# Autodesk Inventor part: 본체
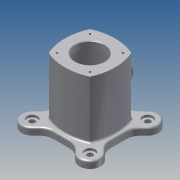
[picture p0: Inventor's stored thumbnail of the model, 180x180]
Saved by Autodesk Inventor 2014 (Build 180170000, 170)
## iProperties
Created: 2016-05
Part Number: 본체
Material: 알루미늄 6061
Document SubType Name: Modeling
Designer: 702
Density: 2.71 g/cm^3
Appearance: 알루미늄 - 평지
Mass: 1109.03 g
Surface Area: 865.354 cm^2
Volume: 409.236 cm^3
Author: 702
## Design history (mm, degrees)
sketch "스케치1"
  geometry: L1 (-49, -49)-(49, -49); L2 (49, -49)-(49, 49); L3 (49, 49)-(-49, 49); L4 (-49, 49)-(-49, -49); L5 (-49, -49)-(49, 49); L6 (49, -49)-(-49, 49); L7 (0, 0)-(-70, 0); L8 (0, 0)-(-49.497, 49.497); L9 (-36.77, 62.225)-(-23.544, 49); L10 (-62.225, 36.77)-(-49, 23.544); L11 (-49, 23.544)-(-49, 49); L12 (-49, 49)-(-23.544, 49); A1 r 70 centre (0, 0) between (-70, 0) and (-49.497, 49.497); A2 r 18 centre (-49.497, 49.497) between (-35.239, 60.483) and (-60.483, 35.239); A3 r 18 centre (-49.497, 49.497) between (-31.504, 49) and (-35.239, 60.483); A4 r 18 centre (-49.497, 49.497) between (-49, 31.504) and (-31.504, 49); A5 r 18 centre (-49.497, 49.497) between (-60.483, 35.239) and (-49, 31.504); 1 further point
  constraints: 24 end point, 18 point on circle, 6 tangent, 5 centre point, 4 midpoint, 4 point on line, 2 coincident, 2 collinear, 2 parallel, 2 perpendicular, 1 horizontal
  dimensions: "d0" = 98 distance of L2.end L3.end; "d1" = 98 distance of L1.end L2.end; "d2" = 140 diameter of A1; "d3" = 45 deg angle of L7 L8; "d4" = 36 diameter of A2; "d5" = 45 deg angle of L3 L9; "d6" = 45 deg angle of L10 L4
extrude "돌출1" new body sketch "스케치1" distance "d7" = 12; taper "d8" = 0 deg
extrude "돌출2" join sketch "스케치1" distance "d9" = 12; taper "d10" = 0 deg
hole "구멍1" diameter "d13" = 10; stored, may be unused: countersink angle "d17" = 90 deg, drill point angle "d19" = 118 deg; dims "d11" = 10, "d12" = 10, "d14" = 6, "d15" = 18, "d16" = 4, "d18" = 8
sketch "스케치3"
  geometry: L1 (-23.544, -49)-(-36.77, -62.225) reference; L2 (23.544, -49)-(-23.544, -49) reference; L3 (-40, 0)-(0, 0); L4 (0, 0)-(-28.284, 28.284); A1 r 40 centre (0, 0) between (-40, 0) and (-28.284, 28.284); 2 further points
  constraints: 4 end point, 2 coincident, 2 point on circle, 1 centre point, 1 parallel, 1 perpendicular
  dimensions: "d24" = 80 diameter of A1
hole "구멍2" sketch "스케치3" at (-28.284, 28.284) diameter "d25" = 3.242; stored, may be unused: countersink angle "d29" = 90 deg, drill point angle "d31" = 118 deg; dims "d26" = 7, "d27" = 4, "d28" = 2, "d30" = 10
sketch "스케치4"
  geometry: L1 (43, -43)-(-43, -43); L2 (-43, -43)-(-43, 43); L3 (-43, 43)-(43, 43); L4 (43, 43)-(43, -43); L5 (43, -43)-(-43, 43); L6 (-43, -43)-(43, 43); L7 (-35.355, -35.355)-(35.355, 35.355); L8 (-35.355, 35.355)-(35.355, -35.355); L9 (-23.544, -49)-(23.544, -49); A1 r 85.579 centre (0, -42.579) between (35.355, 35.355) and (-35.355, 35.355); A2 r 85.579 centre (42.579, 0) between (-35.355, 35.355) and (-35.355, -35.355); A3 r 85.579 centre (-42.579, 0) between (35.355, -35.355) and (35.355, 35.355); A4 r 85.579 centre (0, 42.579) between (-35.355, -35.355) and (35.355, -35.355); 3 further points
  constraints: 18 end point, 8 point on circle, 6 midpoint, 4 centre point, 4 point on line, 4 tangent, 2 collinear, 1 parallel, 1 perpendicular
  dimensions: "d43" = 86 distance of L2.end L3.end; "d44" = 86 distance of L3.end L1.start; "d52" = 100 distance of L7.end L7.start; "d53" = 100 distance of L8.start L8.end
extrude "돌출3" join sketch "스케치4" distance "d54" = 98; taper "d55" = 0 deg
sketch "스케치5"
  geometry: L1 (-49, 0)-(-49, 12) reference; L2 (-49, 12)-(-43, 12) reference; L3 (-43, 110)-(43, 110) reference; L4 (43, 110)-(43, 12) reference; L5 (43, 12)-(49, 12) reference; L6 (49, 12)-(49, 0) reference; L7 (49, 0)-(-49, 0) reference; L8 (-49, 0)-(-49, 12) reference; L9 (-49, 12)-(-43, 12) reference; L10 (-43, 110)-(43, 110) reference; L11 (43, 110)-(43, 12) reference; L12 (43, 12)-(49, 12) reference; L13 (49, 12)-(49, 0) reference; L14 (49, 0)-(-49, 0) reference; L15 (25, 110)-(25, 98); L16 (25, 98)-(35, 98); L17 (35, 98)-(35, 12); L18 (35, 12)-(25, 12); L19 (25, 12)-(25, 0); L20 (0, 0)-(0, 110); L21 (-43, 12)-(-43, 110) reference; L22 (-43, 12)-(-43, 110) reference
  constraints: 12 end point, 3 parallel, 2 perpendicular, 2 point on line, 1 collinear, 1 midpoint
  dimensions: "d60" = 12 distance between parallel lines of L16 L3; "d61" = 12 distance of L18.end L19.end; "d62" = 86 distance of L16.end L17.end (derived); "d63" = 25 distance between parallel lines of L20 L15; "d64" = 35 distance between parallel lines of L20 L17; "d65" = 25 distance between parallel lines of L20 L19
revolve "회전1" sketch "스케치5" stored, may be unused: angle "d66" = 90 deg
sketch "스케치6" dims "d67" = 80
  geometry: L1 (-42.579, 0)-(0, 0); L2 (-35.355, 35.355)-(0, 0); C1 r 25 at (0, 0) reference; A1 r 85.579 centre (-42.579, 0) between (35.355, -35.355) and (35.355, 35.355) reference; 2 further points
  constraints: 4 end point, 1 coincident, 1 horizontal, 1 point on line, 3 other
hole "구멍3" sketch "스케치6" at (-28.284, 28.284) diameter "d68" = 3.242; stored, may be unused: countersink angle "d72" = 90 deg, drill point angle "d74" = 118 deg; dims "d69" = 7, "d70" = 4, "d71" = 2, "d73" = 10
sketch "스케치7"
  geometry: L1 (49, 12)-(49, 0) reference; L2 (49, 0)-(25, 0) reference; L3 (25, 0)-(25, 12) reference; L4 (25, 12)-(35, 12) reference; L5 (35, 12)-(35, 98) reference; L6 (35, 98)-(25, 98) reference; L7 (25, 98)-(25, 110) reference; L8 (25, 110)-(43, 110) reference; L9 (43, 110)-(43, 12) reference; L10 (43, 12)-(49, 12) reference; L11 (-49, 0)-(-49, 12) reference; L12 (-49, 12)-(-43, 12) reference; L13 (-43, 110)-(-25, 110) reference; L14 (-25, 110)-(-25, 98) reference; L15 (-25, 98)-(-35, 98) reference; L16 (-35, 98)-(-35, 12) reference; L17 (-35, 12)-(-25, 12) reference; L18 (-25, 12)-(-25, 0) reference; L19 (-25, 0)-(-49, 0) reference; L20 (35, 84.527)-(55, 81); L21 (55, 81)-(55, 61); L22 (55, 61)-(35, 61); L23 (-43, 12)-(-43, 110) reference; 1 further point
  constraints: 6 end point, 2 perpendicular, 2 point on line
  dimensions: "d79" = 49 distance between parallel lines of L8 L22; "d81" = 100 deg angle of L5 L20; "d82" = 55 distance from line of point (0, 0) L21; "d93" = 20 distance of L20.end L21.end
revolve "회전2" sketch "스케치7" stored, may be unused: angle "d83" = 90 deg
hole "구멍4" diameter "d86" = 25; stored, may be unused: countersink angle "d90" = 90 deg, drill point angle "d92" = 118 deg; dims "d84" = 10, "d85" = 10, "d87" = 7, "d88" = 30, "d89" = 8, "d91" = 50
fillet "모깎기1" dims "d94" = 25
fillet "모깎기2" dims "d95" = 3
fillet "모깎기3" dims "d96" = 3
fillet "모깎기4" dims "d97" = 3
fillet "모깎기5" dims "d98" = 3
chamfer "모따기1" distance "d99" = 1; stored, may be unused: second distance "d100" = 2, angle "d101" = 45 deg
node "작업 평면1"
sketch "스케치8"
  geometry: L1 (34.285, 110)-(-34.285, 110) reference; 2 further points
  constraints: 1 other
  dimensions: "d103" = 49 distance from line of point (-29, 61) L1; "d104" = 29 horizontal distance of point (0, 0) point (-29, 61)
feature "엠보싱1" sketch "스케치8" dims "d0" = 98, "d1" = 98, "d2" = 140, "d3" = 45 deg, "d4" = 36, "d5" = 45 deg, "d6" = 45 deg, "d105" = 0.5, "d106" = 0
fillet "모깎기6" dims "d107" = 3
node "솔리드1"
pattern_circular "원형 패턴1" dims angle "d22" = 360 deg
pattern_circular "원형 패턴2" dims angle "d33" = 360 deg
pattern_circular "원형 패턴3" dims angle "d76" = 360 deg
node "절단 모서리 투영1"
node "절단 모서리 투영2"
node "절단 모서리 투영3"
other parameters: "d102" = 59
